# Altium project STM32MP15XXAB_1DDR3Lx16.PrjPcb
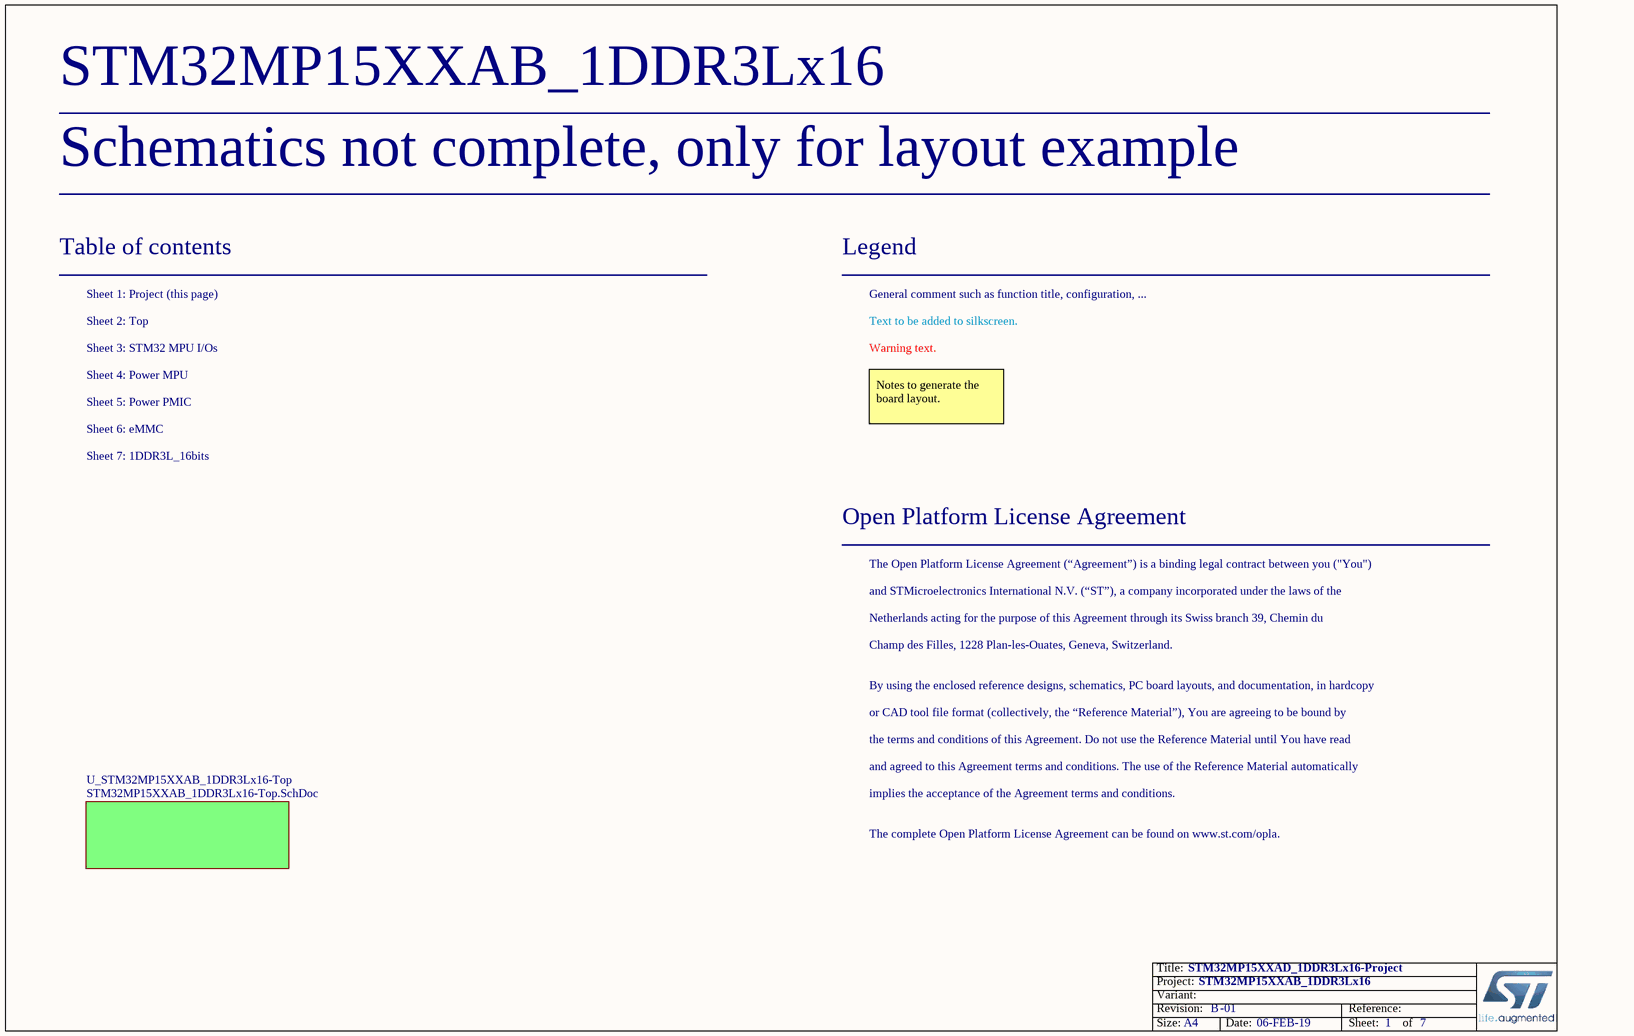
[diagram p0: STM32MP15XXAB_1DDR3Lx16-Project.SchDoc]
Board_Assembly_Revision: 01; Board_Document_Date: 06-FEB-19; Board_Name: STM32MP15XXAB_1DDR3Lx16; Board_PCB_Revision: B
7 sheets, 144 parts. Net scope: flat (ports and power ports of the same name join across sheets).
Board file: STM32MP15XXAB_1DDR3Lx16_B01.PcbDoc
Sheets:
  STM32MP15XXAB_1DDR3Lx16-Project.SchDoc
    U_STM32MP15XXAB_1DDR3Lx16-Top = STM32MP15XXAB_1DDR3Lx16-Top.SchDoc
      U_Power_PMIC = Power_PMIC.SchDoc
      U_Power_MPU = Power_MPU.SchDoc
      U_eMMC = eMMC.SchDoc
      U_STM32_MPU_IOs = STM32_MPU_IOs.SchDoc
      U_1DDR3L_16bits = 1DDR3L_16bits.SchDoc

## Sheet STM32MP15XXAB_1DDR3Lx16-Project.SchDoc: STM32MP15XXAD_1DDR3Lx16-Project
size A4; ApprovedBy: Not used; CheckedBy: Not used; Author: Not used; CompanyName: STMicroelectronics; DrawnBy: Not used; Engineer: Not used; Organization: Not used; Address1: Not used; Address2: Not used; Address3: Not used; Address4: Not used; DocumentNumber: Not used; Revision: Not used; SheetNumber: 1; SheetTotal: 7

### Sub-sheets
U_STM32MP15XXAB_1DDR3Lx16-Top = STM32MP15XXAB_1DDR3Lx16-Top.SchDoc: no entries

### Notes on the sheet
- Schematics not complete, only for layout example
- Table of contents
- Sheet 1: Project (this page)
- Legend
- General comment such as function title, configuration, ...
- Sheet 2: Top
- Sheet 3: STM32 MPU I/Os
- Sheet 4: Power MPU
- Text to be added to silkscreen.
- Warning text.
- Sheet 5: Power PMIC
- Sheet 6: eMMC
- Notes to generate the board layout.
- Sheet 7: 1DDR3L_16bits
- Open Platform License Agreement
- The Open Platform License Agreement (“Agreement”) is a binding legal contract between you ("You")
- and STMicroelectronics International N.V. (“ST”), a company incorporated under the laws of the
- Netherlands acting for the purpose of this Agreement through its Swiss branch 39, Chemin du
- Champ des Filles, 1228 Plan-les-Ouates, Geneva, Switzerland.
- By using the enclosed reference designs, schematics, PC board layouts, and documentation, in hardcopy
- or CAD tool file format (collectively, the “Reference Material”), You are agreeing to be bound by
- the terms and conditions of this Agreement. Do not use the Reference Material until You have read
- and agreed to this Agreement terms and conditions. The use of the Reference Material automatically
- implies the acceptance of the Agreement terms and conditions.
- The complete Open Platform License Agreement can be found on www.st.com/opla.

## Sheet STM32MP15XXAB_1DDR3Lx16-Top.SchDoc: STM32MP15XXAD_1DDR3Lx16-TOP
size A4; Date: Not used; ApprovedBy: Not used; CheckedBy: Not used; Author: Not used; CompanyName: STMicroelectronics; DrawnBy: Not used; Engineer: Not used; Organization: Not used; Address1: Not used; Address2: Not used; Address3: Not used; Address4: Not used; DocumentNumber: Not used; Revision: Not used; SheetNumber: 2; SheetTotal: 7
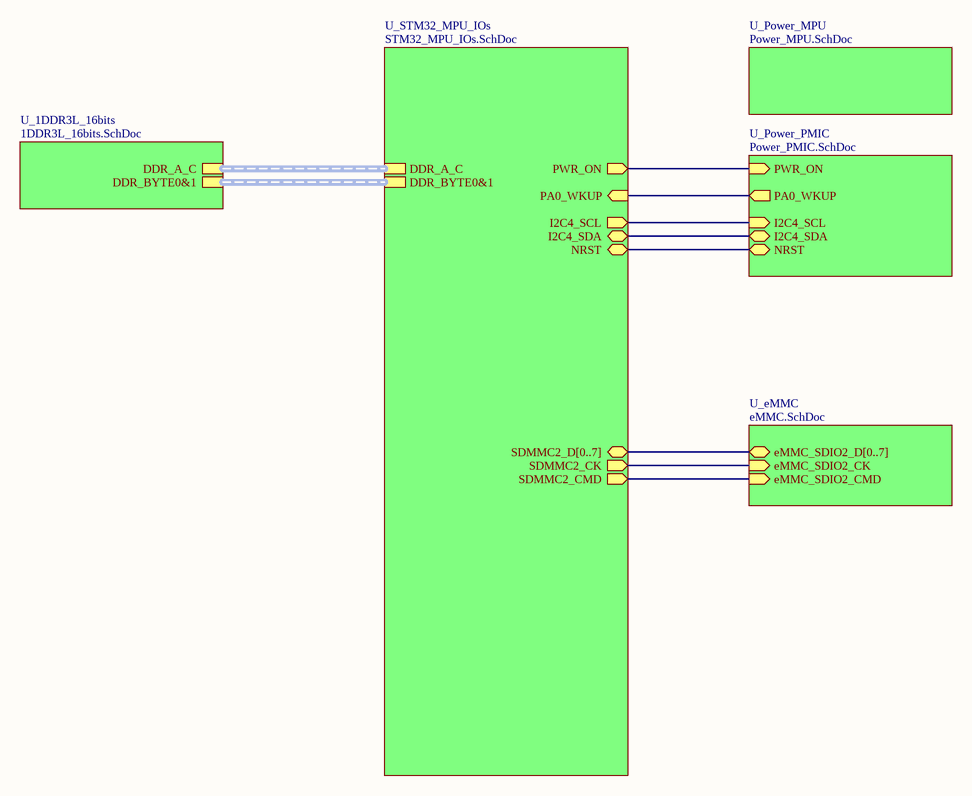
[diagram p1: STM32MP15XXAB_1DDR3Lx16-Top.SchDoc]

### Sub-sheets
U_1DDR3L_16bits = 1DDR3L_16bits.SchDoc: DDR_BYTE0&1 (harness DDR_BYTE_0&1), DDR_A_C (harness DDR_A_C)
U_eMMC = eMMC.SchDoc: eMMC_SDIO2_CK (in), eMMC_SDIO2_D[0..7] (bidir), eMMC_SDIO2_CMD (in)
U_Power_MPU = Power_MPU.SchDoc: no entries
U_Power_PMIC = Power_PMIC.SchDoc: I2C4_SDA (bidir), I2C4_SCL (in), PA0_WKUP (out), NRST (bidir), PWR_ON (in)
U_STM32_MPU_IOs = STM32_MPU_IOs.SchDoc: PA0_WKUP (in), NRST (bidir), PWR_ON (out), I2C4_SCL (out), I2C4_SDA (bidir), DDR_BYTE0&1 (harness DDR_BYTE_0&1), DDR_A_C (harness DDR_A_C), SDMMC2_D[0..7] (bidir), SDMMC2_CMD (out), SDMMC2_CK (out)

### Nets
(unnamed): sheet U_Power_PMIC/I2C4_SDA, sheet U_STM32_MPU_IOs/I2C4_SDA
(unnamed): sheet U_Power_PMIC/I2C4_SCL, sheet U_STM32_MPU_IOs/I2C4_SCL  [a separate net that carries the same name]
(unnamed): sheet U_Power_PMIC/PA0_WKUP, sheet U_STM32_MPU_IOs/PA0_WKUP  [a separate net that carries the same name]
(unnamed): sheet U_Power_PMIC/NRST, sheet U_STM32_MPU_IOs/NRST  [a separate net that carries the same name]
(unnamed): sheet U_Power_PMIC/PWR_ON, sheet U_STM32_MPU_IOs/PWR_ON  [a separate net that carries the same name]
(unnamed): sheet U_eMMC/eMMC_SDIO2_CK, sheet U_STM32_MPU_IOs/SDMMC2_CK  [a separate net that carries the same name]
(unnamed): sheet U_eMMC/eMMC_SDIO2_CMD, sheet U_STM32_MPU_IOs/SDMMC2_CMD  [a separate net that carries the same name]

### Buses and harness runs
bus sheet U_eMMC/eMMC_SDIO2_D[0..7] = sheet U_STM32_MPU_IOs/SDMMC2_D[0..7]
harness sheet U_1DDR3L_16bits/DDR_A_C = sheet U_STM32_MPU_IOs/DDR_A_C
harness sheet U_1DDR3L_16bits/DDR_BYTE0&1 = sheet U_STM32_MPU_IOs/DDR_BYTE0&1

## Sheet Power_PMIC.SchDoc: Power_PMIC
size A3; CompanyName: STMicroelectronics; Organization: Microcontrollers Division; Address1: 12, Rue Jules HOROWITZ; Address2: 38019 Grenoble; Address3: FRANCE; SheetNumber: 5; SheetTotal: 7
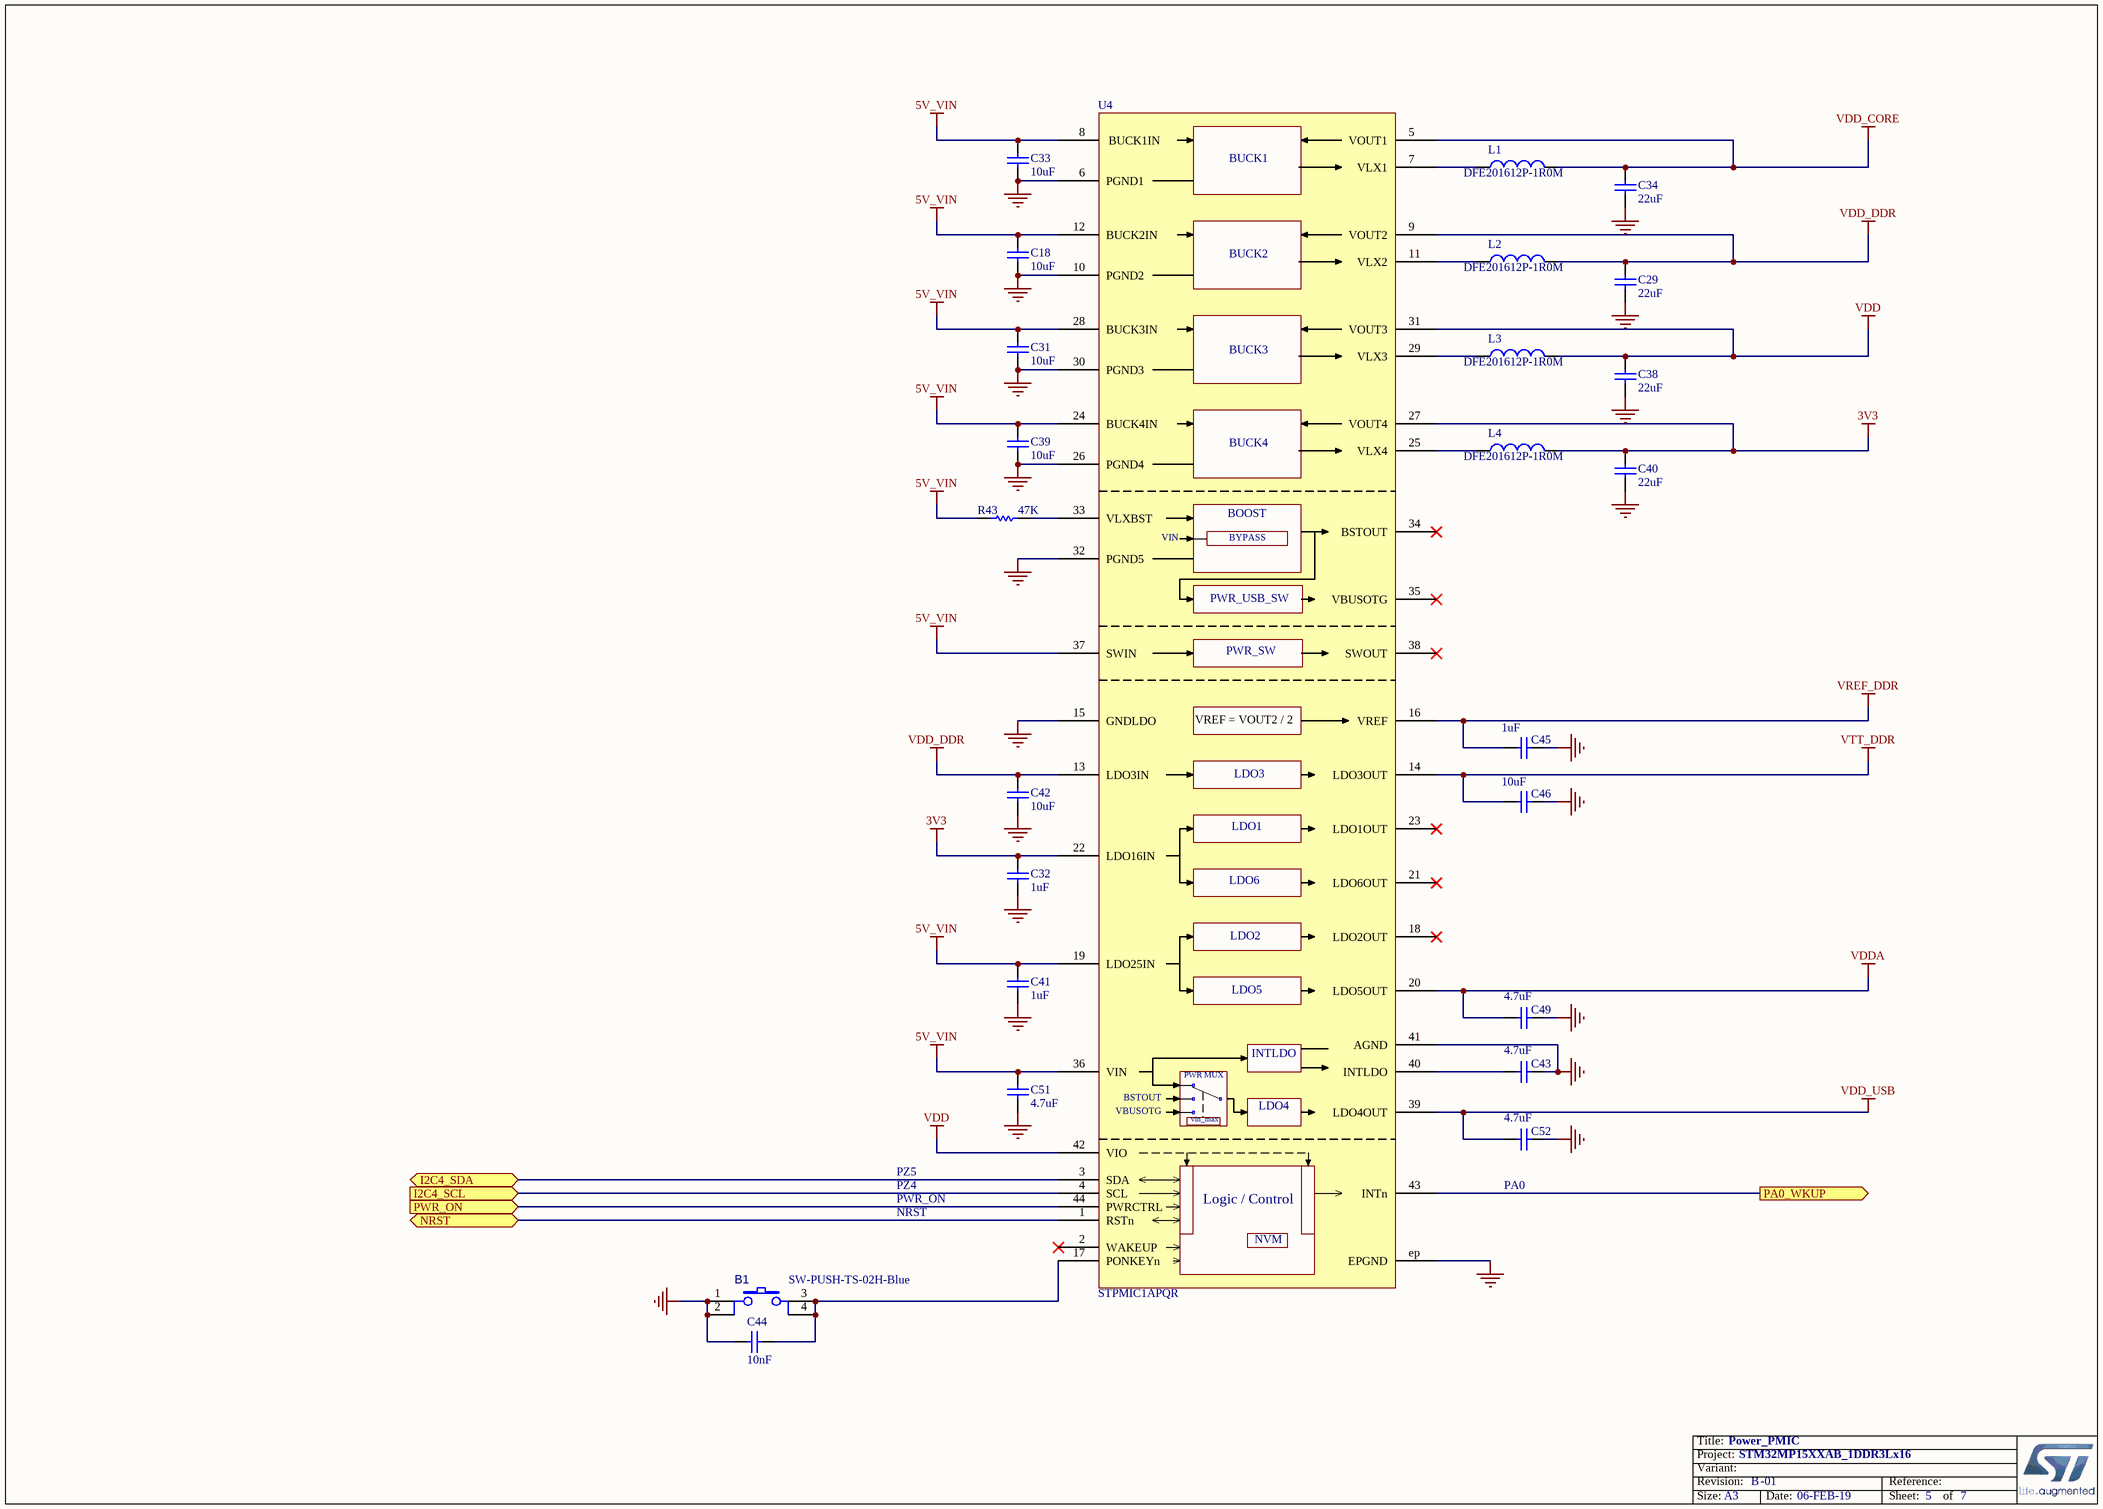
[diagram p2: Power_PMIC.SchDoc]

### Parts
B1  value SW-PUSH-TS-02H-Blue  [SWI_JIUBABA_C-TS-02H-2-5-B-V-T_R_BLUE]
C18  value 10uF  [C0603]
C29  value 22uF  [C0603]
C31  value 10uF  [C0603]
C32  value 1uF  [C0402]
C33  value 10uF  [C0603]
C34  value 22uF  [C0603]
C38  value 22uF  [C0603]
C39  value 10uF  [C0603]
C40  value 22uF  [C0603]
C41  value 1uF  [C0402]
C42  value 10uF  [C0603]
C43  value 4.7uF  [C0402]
C44  value 10nF  [C0402]
C45  value 1uF  [C0402]
C46  value 10uF  [C0603]
C49  value 4.7uF  [C0402]
C51  value 4.7uF  [C0402]
C52  value 4.7uF  [C0402]
L1  value DFE201612P-1R0M  [IND_MURATA_DFE201612P]
L2  value DFE201612P-1R0M  [IND_MURATA_DFE201612P]
L3  value DFE201612P-1R0M  [IND_MURATA_DFE201612P]
L4  value DFE201612P-1R0M  [IND_MURATA_DFE201612P]
R43  value 47K  [R0402]
U4  value STPMIC1APQR  [ICC_WFQFN44-EPAD_5X6_P040]

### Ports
I2C4_SCL (in), I2C4_SDA (bidir), NRST (bidir), PA0_WKUP (out), PWR_ON (in)

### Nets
3V3: C32.2 C40.2 L4.2 U4.22(LDO16IN) U4.27(VOUT4)
5V_VIN: C18.2 C31.2 C33.2 C39.2 C41.2 C51.1 R43.2 U4.8(BUCK1IN) U4.12(BUCK2IN) U4.19(LDO25IN) U4.24(BUCK4IN) U4.28(BUCK3IN) U4.36(VIN) U4.37(SWIN)
GND: B1.1 B1.2 C18.1 C29.1 C31.1 C32.1 C33.1 C34.1 C38.1 C39.1 C40.1 C41.1 C42.1 C43.1 C44.1 C45.1 C46.1 C49.1 C51.2 C52.1 U4.6(PGND1) U4.10(PGND2) U4.15(GNDLDO) U4.26(PGND4) U4.30(PGND3) U4.32(PGND5) U4.41(AGND) U4.ep(EPGND)
VDD: C38.2 L3.2 U4.31(VOUT3) U4.42(VIO)
VDD_CORE: C34.2 L1.2 U4.5(VOUT1)
VDD_DDR: C29.2 C42.2 L2.2 U4.9(VOUT2) U4.13(LDO3IN)
VDD_USB: C52.2 U4.39(LDO4OUT)
VDDA: C49.2 U4.20(LDO5OUT)
VREF_DDR: C45.2 U4.16(VREF)
VTT_DDR: C46.2 U4.14(LDO3OUT)
I2C4_SCL: U4.4(SCL) ; port I2C4_SCL
I2C4_SDA: U4.3(SDA) ; port I2C4_SDA
NRST: U4.1(RSTn) ; port NRST
PA0_WKUP: U4.43(INTn) ; port PA0_WKUP
PWR_ON: U4.44(PWRCTRL) ; port PWR_ON
NetB1_3: B1.3 B1.4 C44.2 U4.17(PONKEYn)
NetC43_2: C43.2 U4.40(INTLDO)
NetL1_1: L1.1 U4.7(VLX1)
NetL2_1: L2.1 U4.11(VLX2)
NetL3_1: L3.1 U4.29(VLX3)
NetL4_1: L4.1 U4.25(VLX4)
NetR43_1: R43.1 U4.33(VLXBST)

Not connected (* = marked no-connect by the designer): U4 2(WAKEUP)* 18(LDO2OUT)* 21(LDO6OUT)* 23(LDO1OUT)* 34(BSTOUT)* 35(VBUSOTG)* 38(SWOUT)*

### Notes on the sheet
- PZ5
- PZ4
- (near C52) PA0
- NRST
- PWR_ON

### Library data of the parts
B1 = MCD-00172: Switch HW SMD blue; Part_Type: Misc; Manufacturer_Part_Number: C-TS-02H-2.5-B-V-T/R BLUE; Manufacturer: JIUBABA; Provided_By: SUBCO
C18 C31 C33 C39 C42 C46 = MCD-00099: Capacitor, MLCC, 10uF, 10V, X5R, 10%, 0603, T=0,8mm; Manufacturer_Part_Number: GRM188R61A106KE69D; Manufacturer: MURATA; Provided_By: SUBCO; ECCN_US: EAR99; ECCN_EU: NEC
C29 C34 C38 C40 = MCD-00100: Capacitor, MLCC, 22uF, 6V3, X5R, 20%, 0603, T=0,8mm; Manufacturer_Part_Number: GRM188R60J226MEA0J; Manufacturer: MURATA; Provided_By: SUBCO; ECCN_US: EAR99; ECCN_EU: NEC
C32 C41 C45 = MCD-00095: Capacitor, MLCC, 1uF, 6V3, X5R, 10%, 0402, T=0,5mm; Manufacturer_Part_Number: GRM155R61E105KA12; Manufacturer: MURATA; Alternate_Manufacturer_Part_Number: GRM155R60J105KE19; Provided_By: SUBCO; ECCN_US: EAR99; ECCN_EU: NEC
C43 C49 C51 C52 = MCD-01356: Capacitor, MLCC, 4.7uF, 6V3, X5R, 20%, 0402, T=0,5mm; Manufacturer_Part_Number: GRM155R60J475ME47; Manufacturer: MURATA; Provided_By: SUBCO; ECCN_US: EAR99; ECCN_EU: NEC
C44 = MCD-00011: Capacitor, MLCC, 10nF, 16V, X7R, 10%, 0402, T=0.5mm; Manufacturer_Part_Number: CC0402KRX7R7BB103; Manufacturer: YAGEO; Provided_By: SUBCO; ECCN_US: EAR99; ECCN_EU: NEC
L1-L4 = MCD-01491: Inductors 1.0uH 54mOhms3.3A +/-20% 2016; Manufacturer: MURATA; Provided_By: SUBCO
R43 = MCD-00063: Resistor,47K,0402,1%,1/16W; Manufacturer_Part_Number: RC0402FR-0747KL; Manufacturer: YAGEO; Provided_By: SUBCO; ECCN_US: EAR99; ECCN_EU: NEC
U4 = MCD-01650: ST PMIC:  4 step-down + 1 advanced boost SMPS, 6 LDOs, 2 pwr switches, DDR Vref, NVM option 'A' for IO@3.3V; Part_Type: IC; Manufacturer: STMICROELECTRONICS; ECCN_US: EAR99; ECCN_EU: NEC; Provided_By: SUBCO with ST control

## Sheet Power_MPU.SchDoc: Power_MPU
size A3; CompanyName: STMicroelectronics; SheetNumber: 4; SheetTotal: 7
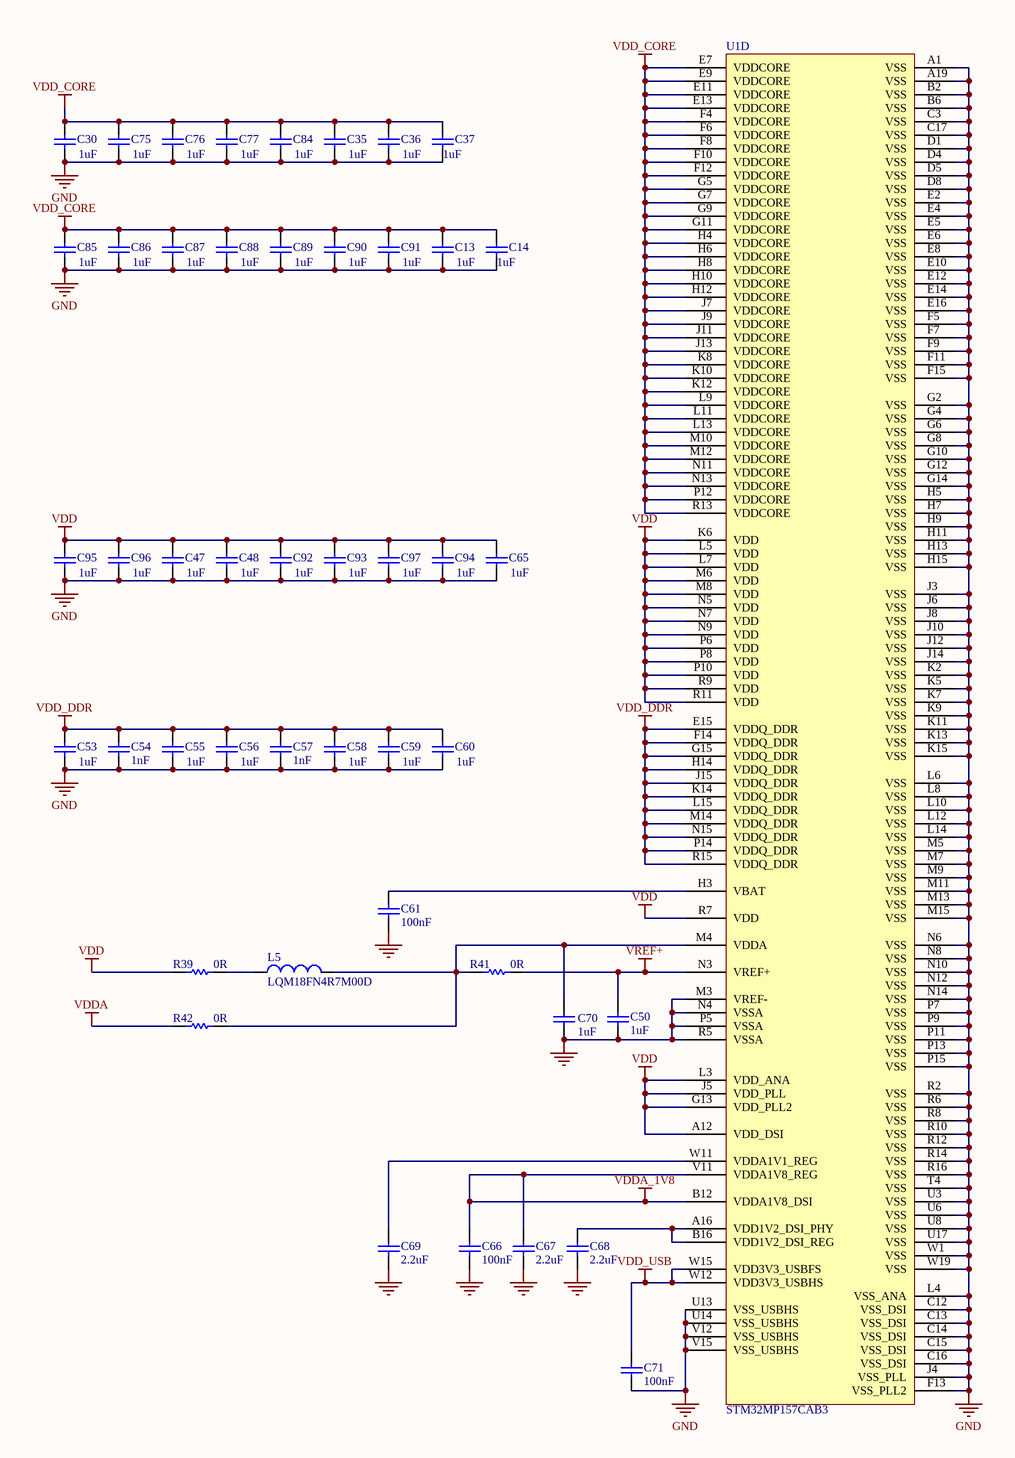
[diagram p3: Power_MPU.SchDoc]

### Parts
C13  value 1uF  [C0402]
C14  value 1uF  [C0402]
C30  value 1uF  [C0402]
C35  value 1uF  [C0402]
C36  value 1uF  [C0402]
C37  value 1uF  [C0402]
C47  value 1uF  [C0402]
C48  value 1uF  [C0402]
C50  value 1uF  [C0402]
C53  value 1uF  [C0402]
C54  value 1nF  [C0402]
C55  value 1uF  [C0402]
C56  value 1uF  [C0402]
C57  value 1nF  [C0402]
C58  value 1uF  [C0402]
C59  value 1uF  [C0402]
C60  value 1uF  [C0402]
C61  value 100nF  [C0402]
C65  value 1uF  [C0402]
C66  value 100nF  [C0402]
C67  value 2.2uF  [C0402]  (hidden comment: Capacitor)
C68  value 2.2uF  [C0402]  (hidden comment: Capacitor)
C69  value 2.2uF  [C0402]  (hidden comment: Capacitor)
C70  value 1uF  [C0402]
C71  value 100nF  [C0402]
C75  value 1uF  [C0402]
C76  value 1uF  [C0402]
C77  value 1uF  [C0402]
C84  value 1uF  [C0402]
C85  value 1uF  [C0402]
C86  value 1uF  [C0402]
C87  value 1uF  [C0402]
C88  value 1uF  [C0402]
C89  value 1uF  [C0402]
C90  value 1uF  [C0402]
C91  value 1uF  [C0402]
C92  value 1uF  [C0402]
C93  value 1uF  [C0402]
C94  value 1uF  [C0402]
C95  value 1uF  [C0402]
C96  value 1uF  [C0402]
C97  value 1uF  [C0402]
L5  value LQM18FN4R7M00D  [L0603_H0P8]
R39  value 0R  [R0402]
R41  value 0R  [R0402]
R42  value 0R  [R0402]
U1  STM32MP157CAB3  [ICC_LFBGA354_16X16_STM32MP157CAB3_P080]  (part D of 5)

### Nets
GND: C13.1 C14.1 C30.1 C35.1 C36.1 C37.1 C47.1 C48.1 C50.1 C53.1 C54.1 C55.1 C56.1 C57.1 C58.1 C59.1 C60.1 C61.1 C65.1 C66.1 C67.1 C68.1 C69.1 C70.1 C71.1 C75.1 C76.1 C77.1 C84.1 C85.1 C86.1 C87.1 C88.1 C89.1 C90.1 C91.1 C92.1 C93.1 C94.1 C95.1 C96.1 C97.1 U1.A1(VSS) U1.A19(VSS) U1.B2(VSS) U1.B6(VSS) U1.C3(VSS) U1.C12(VSS_DSI) U1.C13(VSS_DSI) U1.C14(VSS_DSI) U1.C15(VSS_DSI) U1.C16(VSS_DSI) U1.C17(VSS) U1.D1(VSS) U1.D4(VSS) U1.D5(VSS) U1.D8(VSS) U1.E2(VSS) U1.E4(VSS) U1.E5(VSS) U1.E6(VSS) U1.E8(VSS) U1.E10(VSS) U1.E12(VSS) U1.E14(VSS) U1.E16(VSS) U1.F5(VSS) U1.F7(VSS) U1.F9(VSS) U1.F11(VSS) U1.F13(VSS_PLL2) U1.F15(VSS) U1.G2(VSS) U1.G4(VSS) U1.G6(VSS) U1.G8(VSS) U1.G10(VSS) U1.G12(VSS) U1.G14(VSS) U1.H5(VSS) U1.H7(VSS) U1.H9(VSS) U1.H11(VSS) U1.H13(VSS) U1.H15(VSS) U1.J3(VSS) U1.J4(VSS_PLL) U1.J6(VSS) U1.J8(VSS) U1.J10(VSS) U1.J12(VSS) U1.J14(VSS) U1.K2(VSS) U1.K5(VSS) U1.K7(VSS) U1.K9(VSS) U1.K11(VSS) U1.K13(VSS) U1.K15(VSS) U1.L4(VSS_ANA) U1.L6(VSS) U1.L8(VSS) U1.L10(VSS) U1.L12(VSS) U1.L14(VSS) U1.M3(VREF-) U1.M5(VSS) U1.M7(VSS) U1.M9(VSS) U1.M11(VSS) U1.M13(VSS) U1.M15(VSS) U1.N4(VSSA) U1.N6(VSS) U1.N8(VSS) U1.N10(VSS) U1.N12(VSS) U1.N14(VSS) U1.P5(VSSA) U1.P7(VSS) U1.P9(VSS) U1.P11(VSS) U1.P13(VSS) U1.P15(VSS) U1.R2(VSS) U1.R5(VSSA) U1.R6(VSS) U1.R8(VSS) U1.R10(VSS) U1.R12(VSS) U1.R14(VSS) U1.R16(VSS) U1.T4(VSS) U1.U3(VSS) U1.U6(VSS) U1.U8(VSS) U1.U13(VSS_USBHS) U1.U14(VSS_USBHS) U1.U17(VSS) U1.V12(VSS_USBHS) U1.V15(VSS_USBHS) U1.W1(VSS) U1.W19(VSS)
VDD: C47.2 C48.2 C65.2 C92.2 C93.2 C94.2 C95.2 C96.2 C97.2 R39.1 U1.A12(VDD_DSI) U1.G13(VDD_PLL2) U1.J5(VDD_PLL) U1.K6(VDD) U1.L3(VDD_ANA) U1.L5(VDD) U1.L7(VDD) U1.M6(VDD) U1.M8(VDD) U1.N5(VDD) U1.N7(VDD) U1.N9(VDD) U1.P6(VDD) U1.P8(VDD) U1.P10(VDD) U1.R7(VDD) U1.R9(VDD) U1.R11(VDD)
VDD_CORE: C13.2 C14.2 C30.2 C35.2 C36.2 C37.2 C75.2 C76.2 C77.2 C84.2 C85.2 C86.2 C87.2 C88.2 C89.2 C90.2 C91.2 U1.E7(VDDCORE) U1.E9(VDDCORE) U1.E11(VDDCORE) U1.E13(VDDCORE) U1.F4(VDDCORE) U1.F6(VDDCORE) U1.F8(VDDCORE) U1.F10(VDDCORE) U1.F12(VDDCORE) U1.G5(VDDCORE) U1.G7(VDDCORE) U1.G9(VDDCORE) U1.G11(VDDCORE) U1.H4(VDDCORE) U1.H6(VDDCORE) U1.H8(VDDCORE) U1.H10(VDDCORE) U1.H12(VDDCORE) U1.J7(VDDCORE) U1.J9(VDDCORE) U1.J11(VDDCORE) U1.J13(VDDCORE) U1.K8(VDDCORE) U1.K10(VDDCORE) U1.K12(VDDCORE) U1.L9(VDDCORE) U1.L11(VDDCORE) U1.L13(VDDCORE) U1.M10(VDDCORE) U1.M12(VDDCORE) U1.N11(VDDCORE) U1.N13(VDDCORE) U1.P12(VDDCORE) U1.R13(VDDCORE)
VDD_DDR: C53.2 C54.2 C55.2 C56.2 C57.2 C58.2 C59.2 C60.2 U1.E15(VDDQ_DDR) U1.F14(VDDQ_DDR) U1.G15(VDDQ_DDR) U1.H14(VDDQ_DDR) U1.J15(VDDQ_DDR) U1.K14(VDDQ_DDR) U1.L15(VDDQ_DDR) U1.M14(VDDQ_DDR) U1.N15(VDDQ_DDR) U1.P14(VDDQ_DDR) U1.R15(VDDQ_DDR)
VDD_USB: C71.2 U1.W12(VDD3V3_USBHS) U1.W15(VDD3V3_USBFS)
VDDA: R42.1
VDDA_1V8: C66.2 C67.2 U1.B12(VDDA1V8_DSI) U1.V11(VDDA1V8_REG)
VREF+: C50.2 R41.2 U1.N3(VREF+)
NetC61_2: C61.2 U1.H3(VBAT)
NetC68_2: C68.2 U1.A16(VDD1V2_DSI_PHY) U1.B16(VDD1V2_DSI_REG)
NetC69_2: C69.2 U1.W11(VDDA1V1_REG)
NetC70_2: C70.2 L5.2 R41.1 R42.2 U1.M4(VDDA)
NetL5_1: L5.1 R39.2

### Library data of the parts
C13 C14 C30 C35-C37 C47 C48 C50 C53 C55 C56 C58-C60 C65 C70 C75-C77 C84-C97 = MCD-00095: as C32 on sheet Power_PMIC
C54 C57 = MCD-00198: Capacitor, MLCC, 1nF, 16V, X7R, 10%, 0402, T=0.5mm; Manufacturer_Part_Number: CC0402KRX7R7BB102; Manufacturer: YAGEO; Provided_By: SUBCO; ECCN_US: EAR99; ECCN_EU: NEC
C61 C66 C71 = MCD-00006: Capacitor, MLCC, 100nF, 16V, X7R, 10%, 0402, T=0.5mm; Manufacturer_Part_Number: CC0402KRX7R7BB104; Manufacturer: YAGEO; Alternate_Manufacturer_Part_Number: GCM155R71C104KA55D; Alternate_Manufacturer: MURATA; Provided_By: SUBCO; ECCN_US: EAR99; ECCN_EU: NEC
C67-C69 = MCD-01823: Capacitor,MLCC,2.2uF,6V3,X5R,10%,0402,T=0.5; Manufacturer_Part_Number: GRM155R60J225KE95D; Manufacturer: MURATA; ECCN_US: EAR99; ECCN_EU: NEC; Provided_By: SUBCO
L5 = MCD-01134: IND 4.7uH 20% 80mA 600mhom 0603; Part_Type: Inductor; Manufacturer: MURATA; Provided_By: SUBCO
R39 R41 R42 = MCD-00052: Resistor,0R,0402,5%,1/16W; Manufacturer_Part_Number: RC0402JR-070RL; Manufacturer: YAGEO; Provided_By: SUBCO; ECCN_US: EAR99; ECCN_EU: NEC
U1 = MCD-01805: MPU LFBGA 16x16x1.271 PITCH 0.8 mm secure boot + crypto; Part_Type: IC; Manufacturer: STMICROELECTRONICS; ECCN_US: 5A992C; ECCN_EU: 5A002A4; Provided_By: SUBCO with ST control; Company_Nationality: Netherlands; CCATS: G179243   5A992C 740.17(B)(3) 25-Mar-2019; Component_Country_Of_Origin: Korea (South)

## Sheet eMMC.SchDoc: eMMC
size A3; CompanyName: STMicroelectronics; Address1: 12, Rue Jules HOROWITZ; Address2: 38019 Grenoble; Address3: FRANCE; SheetNumber: 6; SheetTotal: 7
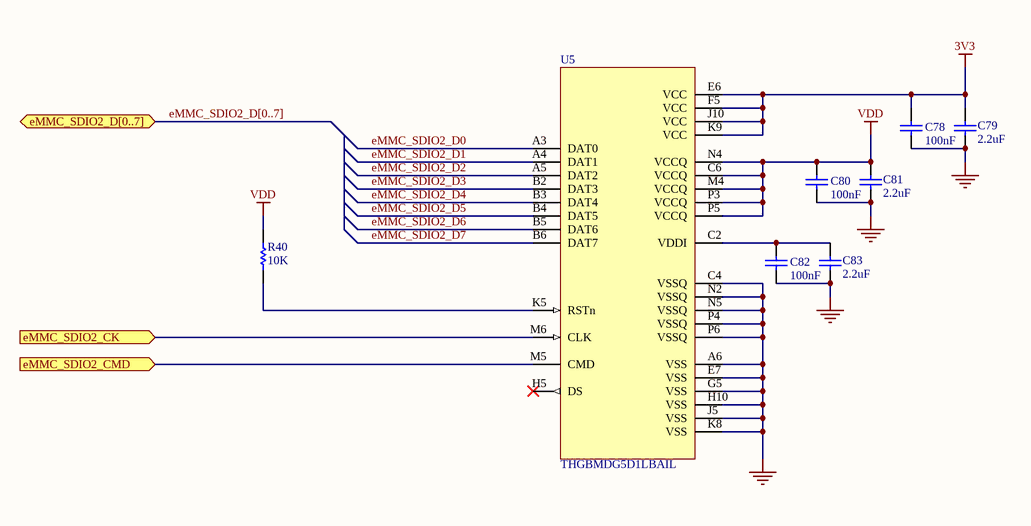
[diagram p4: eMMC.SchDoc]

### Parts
C78  value 100nF  [C0402]
C79  value 2.2uF  [C0603]
C80  value 100nF  [C0402]
C81  value 2.2uF  [C0603]
C82  value 100nF  [C0402]
C83  value 2.2uF  [C0603]
R40  value 10K  [R0402]
U5  value THGBMDG5D1LBAIL  [ICC_P-WFBGA153_13X11P5_P050]

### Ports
eMMC_SDIO2_CK (in), eMMC_SDIO2_CMD (in), eMMC_SDIO2_D[0..7] (bidir)

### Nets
3V3: C78.2 C79.2 U5.E6(VCC) U5.F5(VCC) U5.J10(VCC) U5.K9(VCC)
GND: C78.1 C79.1 C80.1 C81.1 C82.1 C83.1 U5.A6(VSS) U5.C4(VSSQ) U5.E7(VSS) U5.G5(VSS) U5.H10(VSS) U5.J5(VSS) U5.K8(VSS) U5.N2(VSSQ) U5.N5(VSSQ) U5.P4(VSSQ) U5.P6(VSSQ)
VDD: C80.2 C81.2 R40.2 U5.C6(VCCQ) U5.M4(VCCQ) U5.N4(VCCQ) U5.P3(VCCQ) U5.P5(VCCQ)
eMMC_SDIO2_CK: U5.M6(CLK) ; port eMMC_SDIO2_CK
eMMC_SDIO2_CMD: U5.M5(CMD) ; port eMMC_SDIO2_CMD
eMMC_SDIO2_D0: U5.A3(DAT0)
eMMC_SDIO2_D1: U5.A4(DAT1)
eMMC_SDIO2_D2: U5.A5(DAT2)
eMMC_SDIO2_D3: U5.B2(DAT3)
eMMC_SDIO2_D4: U5.B3(DAT4)
eMMC_SDIO2_D5: U5.B4(DAT5)
eMMC_SDIO2_D6: U5.B5(DAT6)
eMMC_SDIO2_D7: U5.B6(DAT7)
NetC82_2: C82.2 C83.2 U5.C2(VDDI)
NetR40_1: R40.1 U5.K5(RSTn)

Not connected (* = marked no-connect by the designer): U5 H5(DS)*

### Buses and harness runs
bus eMMC_SDIO2_D[0..7] = port eMMC_SDIO2_D[0..7]

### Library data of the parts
C78 C80 C82 = MCD-00006: as C61 on sheet Power_MPU
C79 C81 C83 = MCD-00012: Capacitor, MLCC, 2.2uF, 10V, X5R, 10%, 0603, T=0,8mm; Manufacturer_Part_Number: CC0603KRX5R6BB225; Manufacturer: YAGEO; Alternate_Manufacturer_Part_Number: C0603C225K8PACTU; Alternate_Manufacturer: KEMET; Provided_By: SUBCO; ECCN_US: EAR99; ECCN_EU: NEC
R40 = MCD-00053: Resistor,10K,0402,1%,1/16W; Manufacturer_Part_Number: RC0402FR-0710KL; Manufacturer: YAGEO; Provided_By: SUBCO; ECCN_US: EAR99; ECCN_EU: NEC
U5 = MCD-00110: Memory,e-MMC,4GB,3V3,WFBGA,153pins; Part_Type: IC; Manufacturer: TOSHIBA; Provided_By: SUBCO; ECCN_US: 3A991; ECCN_EU: NEC

## Sheet STM32_MPU_IOs.SchDoc: MPU
size A3; SheetNumber: 3; SheetTotal: 7
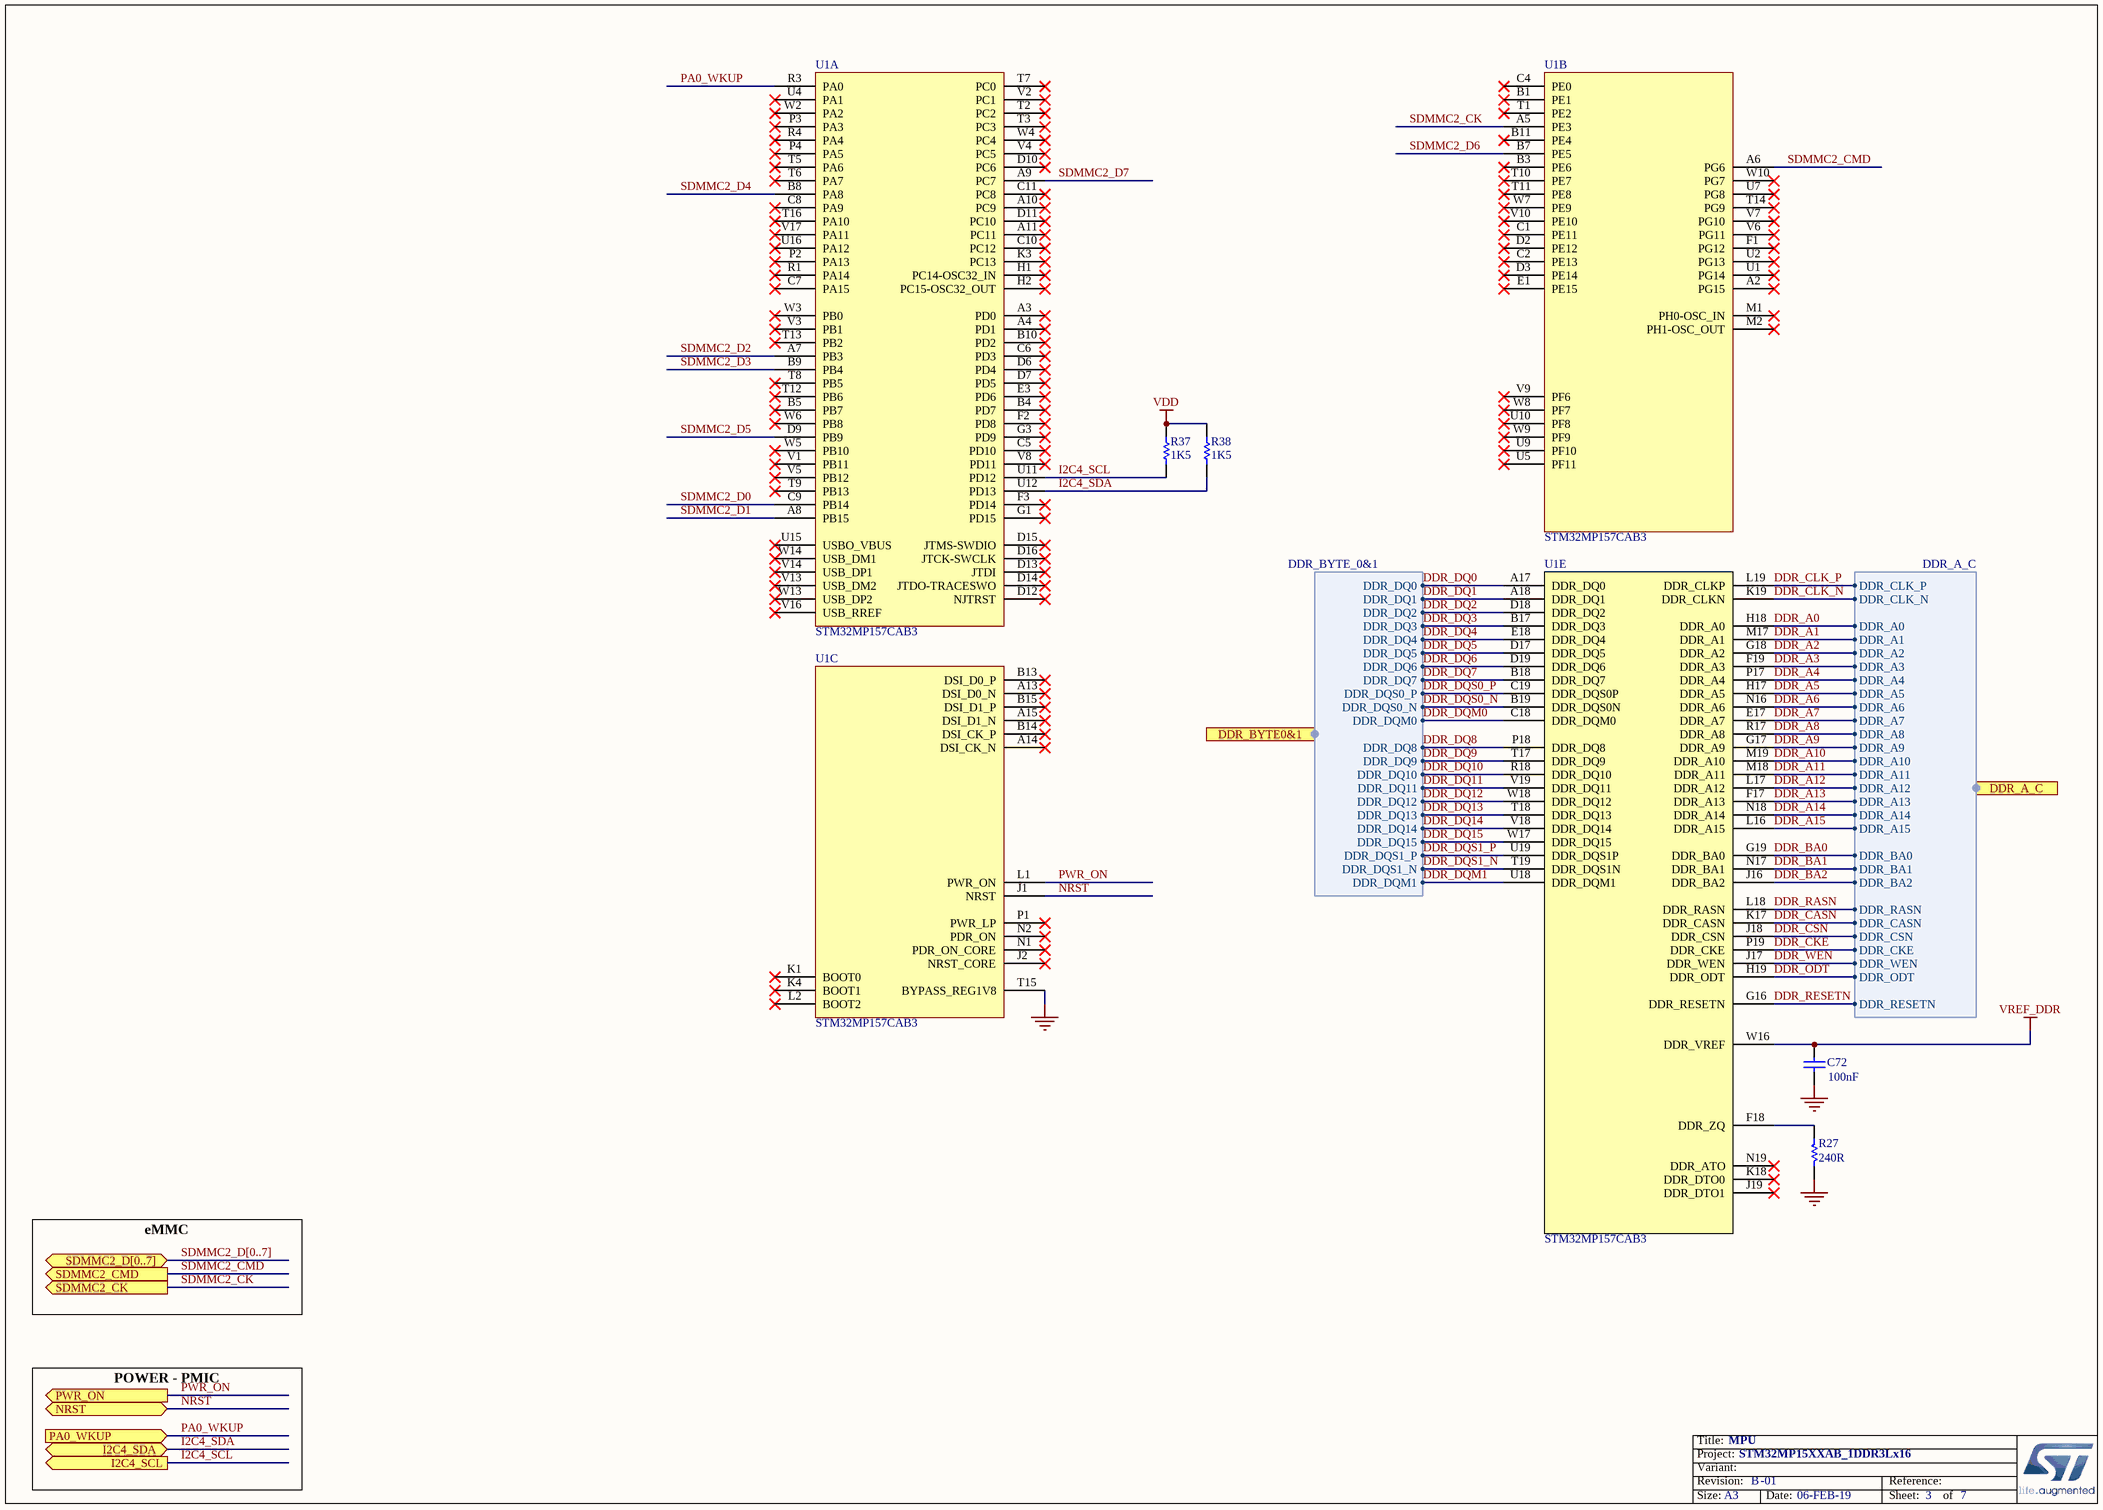
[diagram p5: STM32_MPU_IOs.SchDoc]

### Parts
C72  value 100nF  [C0402]
R27  value 240R  [R0402]
R37  value 1K5  [R0402]
R38  value 1K5  [R0402]
U1  STM32MP157CAB3  [ICC_LFBGA354_16X16_STM32MP157CAB3_P080]  (parts A,B,C,E of 5)

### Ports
DDR_A_C (harness DDR_A_C), DDR_BYTE0&1 (harness DDR_BYTE_0&1), I2C4_SCL (out), I2C4_SDA (bidir), NRST (bidir), PA0_WKUP (in), PWR_ON (out), SDMMC2_CK (out), SDMMC2_CMD (out), SDMMC2_D[0..7] (bidir)

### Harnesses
DDR_BYTE_0&1: DDR_DQ0, DDR_DQ1, DDR_DQ2, DDR_DQ3, DDR_DQ4, DDR_DQ5, DDR_DQ6, DDR_DQ7, DDR_DQS0_P, DDR_DQS0_N, DDR_DQM0, DDR_DQ8, DDR_DQ9, DDR_DQ10, DDR_DQ11, DDR_DQ12, DDR_DQ13, DDR_DQ14, DDR_DQ15, DDR_DQS1_P, DDR_DQS1_N, DDR_DQM1
DDR_A_C: DDR_CLK_P, DDR_CLK_N, DDR_A0, DDR_A1, DDR_A2, DDR_A3, DDR_A4, DDR_A5, DDR_A6, DDR_A7, DDR_A8, DDR_A9, DDR_A10, DDR_A11, DDR_A12, DDR_A13, DDR_A14, DDR_BA0, DDR_BA1, DDR_BA2, DDR_RASN, DDR_CASN, DDR_CSN, DDR_CKE, DDR_WEN, DDR_ODT, DDR_RESETN, DDR_A15

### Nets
GND: C72.1 R27.2 U1.T15(BYPASS_REG1V8)
VDD: R37.1 R38.1
VREF_DDR: C72.2 U1.W16(DDR_VREF)
DDR_A0: U1.H18(DDR_A0) ; port DDR_A_C.DDR_A0
DDR_A1: U1.M17(DDR_A1) ; port DDR_A_C.DDR_A1
DDR_A2: U1.G18(DDR_A2) ; port DDR_A_C.DDR_A2
DDR_A3: U1.F19(DDR_A3) ; port DDR_A_C.DDR_A3
DDR_A4: U1.P17(DDR_A4) ; port DDR_A_C.DDR_A4
DDR_A5: U1.H17(DDR_A5) ; port DDR_A_C.DDR_A5
DDR_A6: U1.N16(DDR_A6) ; port DDR_A_C.DDR_A6
DDR_A7: U1.E17(DDR_A7) ; port DDR_A_C.DDR_A7
DDR_A8: U1.R17(DDR_A8) ; port DDR_A_C.DDR_A8
DDR_A9: U1.G17(DDR_A9) ; port DDR_A_C.DDR_A9
DDR_A10: U1.M19(DDR_A10) ; port DDR_A_C.DDR_A10
DDR_A11: U1.M18(DDR_A11) ; port DDR_A_C.DDR_A11
DDR_A12: U1.L17(DDR_A12) ; port DDR_A_C.DDR_A12
DDR_A13: U1.F17(DDR_A13) ; port DDR_A_C.DDR_A13
DDR_A14: U1.N18(DDR_A14) ; port DDR_A_C.DDR_A14
DDR_A15: U1.L16(DDR_A15) ; port DDR_A_C.DDR_A15
DDR_BA0: U1.G19(DDR_BA0) ; port DDR_A_C.DDR_BA0
DDR_BA1: U1.N17(DDR_BA1) ; port DDR_A_C.DDR_BA1
DDR_BA2: U1.J16(DDR_BA2) ; port DDR_A_C.DDR_BA2
DDR_CASN: U1.K17(DDR_CASN) ; port DDR_A_C.DDR_CASN
DDR_CKE: U1.P19(DDR_CKE) ; port DDR_A_C.DDR_CKE
DDR_CLK_N: U1.K19(DDR_CLKN) ; port DDR_A_C.DDR_CLK_N
DDR_CLK_P: U1.L19(DDR_CLKP) ; port DDR_A_C.DDR_CLK_P
DDR_CSN: U1.J18(DDR_CSN) ; port DDR_A_C.DDR_CSN
DDR_DQ0: U1.A17(DDR_DQ0) ; port DDR_BYTE0&1.DDR_DQ0
DDR_DQ1: U1.A18(DDR_DQ1) ; port DDR_BYTE0&1.DDR_DQ1
DDR_DQ2: U1.D18(DDR_DQ2) ; port DDR_BYTE0&1.DDR_DQ2
DDR_DQ3: U1.B17(DDR_DQ3) ; port DDR_BYTE0&1.DDR_DQ3
DDR_DQ4: U1.E18(DDR_DQ4) ; port DDR_BYTE0&1.DDR_DQ4
DDR_DQ5: U1.D17(DDR_DQ5) ; port DDR_BYTE0&1.DDR_DQ5
DDR_DQ6: U1.D19(DDR_DQ6) ; port DDR_BYTE0&1.DDR_DQ6
DDR_DQ7: U1.B18(DDR_DQ7) ; port DDR_BYTE0&1.DDR_DQ7
DDR_DQ8: U1.P18(DDR_DQ8) ; port DDR_BYTE0&1.DDR_DQ8
DDR_DQ9: U1.T17(DDR_DQ9) ; port DDR_BYTE0&1.DDR_DQ9
DDR_DQ10: U1.R18(DDR_DQ10) ; port DDR_BYTE0&1.DDR_DQ10
DDR_DQ11: U1.V19(DDR_DQ11) ; port DDR_BYTE0&1.DDR_DQ11
DDR_DQ12: U1.W18(DDR_DQ12) ; port DDR_BYTE0&1.DDR_DQ12
DDR_DQ13: U1.T18(DDR_DQ13) ; port DDR_BYTE0&1.DDR_DQ13
DDR_DQ14: U1.V18(DDR_DQ14) ; port DDR_BYTE0&1.DDR_DQ14
DDR_DQ15: U1.W17(DDR_DQ15) ; port DDR_BYTE0&1.DDR_DQ15
DDR_DQM0: U1.C18(DDR_DQM0) ; port DDR_BYTE0&1.DDR_DQM0
DDR_DQM1: U1.U18(DDR_DQM1) ; port DDR_BYTE0&1.DDR_DQM1
DDR_DQS0_N: U1.B19(DDR_DQS0N) ; port DDR_BYTE0&1.DDR_DQS0_N
DDR_DQS0_P: U1.C19(DDR_DQS0P) ; port DDR_BYTE0&1.DDR_DQS0_P
DDR_DQS1_N: U1.T19(DDR_DQS1N) ; port DDR_BYTE0&1.DDR_DQS1_N
DDR_DQS1_P: U1.U19(DDR_DQS1P) ; port DDR_BYTE0&1.DDR_DQS1_P
DDR_ODT: U1.H19(DDR_ODT) ; port DDR_A_C.DDR_ODT
DDR_RASN: U1.L18(DDR_RASN) ; port DDR_A_C.DDR_RASN
DDR_RESETN: U1.G16(DDR_RESETN) ; port DDR_A_C.DDR_RESETN
DDR_WEN: U1.J17(DDR_WEN) ; port DDR_A_C.DDR_WEN
I2C4_SCL: R37.2 U1.U11(PD12) ; port I2C4_SCL
I2C4_SDA: R38.2 U1.U12(PD13) ; port I2C4_SDA
NRST: U1.J1(NRST) ; port NRST
PA0_WKUP: U1.R3(PA0) ; port PA0_WKUP
PWR_ON: U1.L1(PWR_ON) ; port PWR_ON
SDMMC2_CK: U1.A5(PE3) ; port SDMMC2_CK
SDMMC2_CMD: U1.A6(PG6) ; port SDMMC2_CMD
SDMMC2_D0: U1.C9(PB14)
SDMMC2_D1: U1.A8(PB15)
SDMMC2_D2: U1.A7(PB3)
SDMMC2_D3: U1.B9(PB4)
SDMMC2_D4: U1.B8(PA8)
SDMMC2_D5: U1.D9(PB9)
SDMMC2_D6: U1.B7(PE5)
SDMMC2_D7: U1.A9(PC7)
NetR27_1: R27.1 U1.F18(DDR_ZQ)

Not connected (* = marked no-connect by the designer): U1 A2(PG15)* A3(PD0)* A4(PD1)* A10(PC9)* A11(PC11)* A13(DSI_D0_N)* A14(DSI_CK_N)* A15(DSI_D1_N)* B1(PE1)* B3(PE6)* B4(PD7)* B5(PB7)* B10(PD2)* B11(PE4)* B13(DSI_D0_P)* B14(DSI_CK_P)* B15(DSI_D1_P)* C1(PE11)* C2(PE13)* C4(PE0)* C5(PD10)* C6(PD3)* C7(PA15)* C8(PA9)* C10(PC12)* C11(PC8)* D2(PE12)* D3(PE14)* D6(PD4)* D7(PD5)* D10(PC6)* D11(PC10)* D12(NJTRST)* D13(JTDI)* D14(JTDO-TRACESWO)* D15(JTMS-SWDIO)* D16(JTCK-SWCLK)* E1(PE15)* E3(PD6)* F1(PG12)* F2(PD8)* F3(PD14)* G1(PD15)* G3(PD9)* H1(PC14-OSC32_IN)* H2(PC15-OSC32_OUT)* J2(NRST_CORE)* J19(DDR_DTO1)* K1(BOOT0)* K3(PC13)* K4(BOOT1)* K18(DDR_DTO0)* L2(BOOT2)* M1(PH0-OSC_IN)* M2(PH1-OSC_OUT)* N1(PDR_ON_CORE)* N2(PDR_ON)* N19(DDR_ATO)* P1(PWR_LP)* P2(PA13)* P3(PA3)* P4(PA5)* R1(PA14)* R4(PA4)* T1(PE2)* T2(PC2)* T3(PC3)* T5(PA6)* T6(PA7)* T7(PC0)* T8(PB5)* T9(PB13)* T10(PE7)* T11(PE8)* T12(PB6)* T13(PB2)* T14(PG9)* T16(PA10)* U1(PG14)* U2(PG13)* U4(PA1)* U5(PF11)* U7(PG8)* U9(PF10)* U10(PF8)* U15(USBO_VBUS)* U16(PA12)* V1(PB11)* V2(PC1)* V3(PB1)* V4(PC5)* V5(PB12)* V6(PG11)* V7(PG10)* V8(PD11)* V9(PF6)* V10(PE10)* V13(USB_DM2)* V14(USB_DP1)* V16(USB_RREF)* V17(PA11)* W2(PA2)* W3(PB0)* W4(PC4)* W5(PB10)* W6(PB8)* W7(PE9)* W8(PF7)* W9(PF9)* W10(PG7)* W13(USB_DP2)* W14(USB_DM1)*

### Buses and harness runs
bus SDMMC2_D[0..7] = port SDMMC2_D[0..7]

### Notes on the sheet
- eMMC
- POWER - PMIC

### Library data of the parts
C72 = MCD-00006: as C61 on sheet Power_MPU
R27 = MCD-00120: Resistor,240R,0402,1%,1/16W; Manufacturer_Part_Number: RC0402FR-07240RL; Manufacturer: YAGEO; Provided_By: SUBCO; ECCN_US: EAR99; ECCN_EU: NEC
R37 R38 = MCD-00068: Resistor,1K5,0402,1%,1/16W; Manufacturer_Part_Number: RC0402FR-071K5L; Manufacturer: YAGEO; Provided_By: SUBCO; ECCN_US: EAR99; ECCN_EU: NEC
U1 = MCD-01805: as U1 on sheet Power_MPU

## Sheet 1DDR3L_16bits.SchDoc: 1DDR3L_16bits
size A3; Date: Not used; ApprovedBy: Not used; CheckedBy: Not used; Author: Not used; CompanyName: STMicroelectronics; DrawnBy: Not used; Engineer: Not used; Organization: Not used; Address1: Not used; Address2: Not used; Address3: Not used; Address4: Not used; DocumentNumber: Not used; Revision: Not used; SheetNumber: 7; SheetTotal: 7
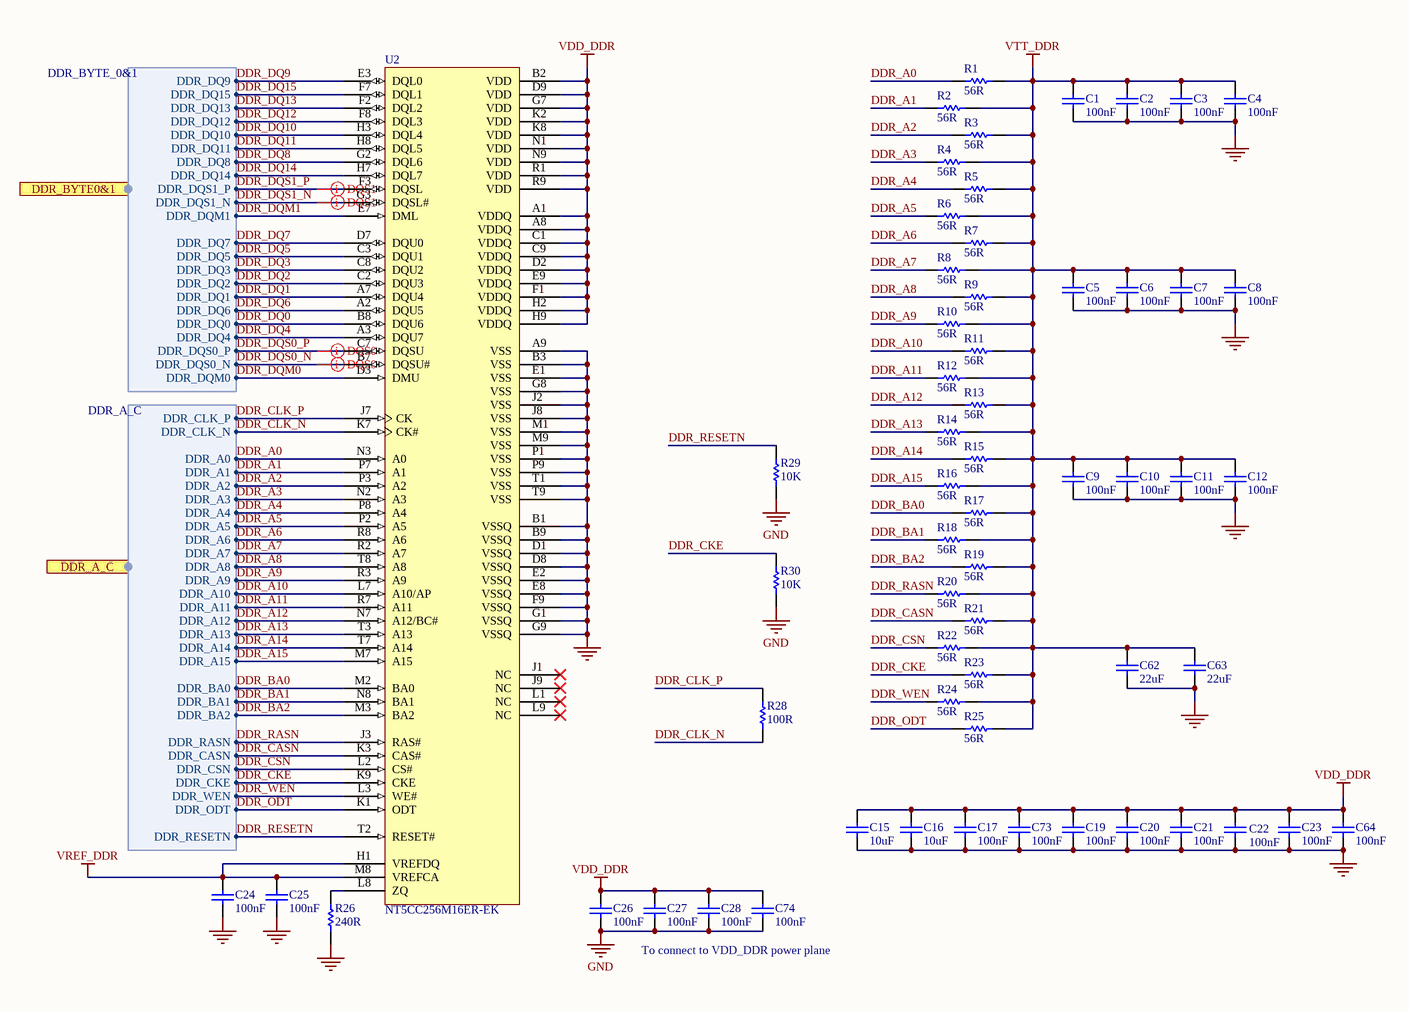
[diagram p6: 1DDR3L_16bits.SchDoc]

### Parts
C1  value 100nF  [C0402]
C2  value 100nF  [C0402]
C3  value 100nF  [C0402]
C4  value 100nF  [C0402]
C5  value 100nF  [C0402]
C6  value 100nF  [C0402]
C7  value 100nF  [C0402]
C8  value 100nF  [C0402]
C9  value 100nF  [C0402]
C10  value 100nF  [C0402]
C11  value 100nF  [C0402]
C12  value 100nF  [C0402]
C15  value 10uF  [C0603]
C16  value 10uF  [C0603]
C17  value 100nF  [C0402]
C19  value 100nF  [C0402]
C20  value 100nF  [C0402]
C21  value 100nF  [C0402]
C22  value 100nF  [C0402]
C23  value 100nF  [C0402]
C24  value 100nF  [C0402]
C25  value 100nF  [C0402]
C26  value 100nF  [C0402]
C27  value 100nF  [C0402]
C28  value 100nF  [C0402]
C62  value 22uF  [C0603]
C63  value 22uF  [C0603]
C64  value 100nF  [C0402]
C73  value 100nF  [C0402]
C74  value 100nF  [C0402]
R1  value 56R  [R0402]
R2  value 56R  [R0402]
R3  value 56R  [R0402]
R4  value 56R  [R0402]
R5  value 56R  [R0402]
R6  value 56R  [R0402]
R7  value 56R  [R0402]
R8  value 56R  [R0402]
R9  value 56R  [R0402]
R10  value 56R  [R0402]
R11  value 56R  [R0402]
R12  value 56R  [R0402]
R13  value 56R  [R0402]
R14  value 56R  [R0402]
R15  value 56R  [R0402]
R16  value 56R  [R0402]
R17  value 56R  [R0402]
R18  value 56R  [R0402]
R19  value 56R  [R0402]
R20  value 56R  [R0402]
R21  value 56R  [R0402]
R22  value 56R  [R0402]
R23  value 56R  [R0402]
R24  value 56R  [R0402]
R25  value 56R  [R0402]
R26  value 240R  [R0402]
R28  value 100R  [R0402]
R29  value 10K  [R0402]
R30  value 10K  [R0402]
U2  value NT5CC256M16ER-EK  [ICC_VFBGA96_9x13_P080]

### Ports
DDR_A_C (harness DDR_A_C), DDR_BYTE0&1 (harness DDR_BYTE_0&1)

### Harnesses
DDR_BYTE_0&1: DDR_DQ10, DDR_DQ9, DDR_DQ13, DDR_DQ15, DDR_DQ8, DDR_DQ12, DDR_DQ11, DDR_DQ14, DDR_DQS1_P, DDR_DQS1_N, DDR_DQ3, DDR_DQM1, DDR_DQ7, DDR_DQ1, DDR_DQ5, DDR_DQ2, DDR_DQ6, DDR_DQ0, DDR_DQ4, DDR_DQS0_P, DDR_DQS0_N, DDR_DQM0
DDR_A_C: DDR_A4, DDR_A0, DDR_A2, DDR_A1, DDR_A6, DDR_A3, DDR_A5, DDR_A7, DDR_A8, DDR_A9, DDR_A14, DDR_A10, DDR_A12, DDR_A11, DDR_BA0, DDR_A13, DDR_A15, DDR_BA1, DDR_BA2, DDR_RASN, DDR_CASN, DDR_CSN, DDR_CKE, DDR_WEN, DDR_ODT, DDR_CLK_P, DDR_CLK_N, DDR_RESETN

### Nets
GND: C1.1 C2.1 C3.1 C4.1 C5.1 C6.1 C7.1 C8.1 C9.1 C10.1 C11.1 C12.1 C15.1 C16.1 C17.1 C19.1 C20.1 C21.1 C22.2 C23.1 C24.1 C25.1 C26.1 C27.1 C28.1 C62.1 C63.1 C64.1 C73.1 C74.1 R26.1 R29.1 R30.1 U2.A9(VSS) U2.B1(VSSQ) U2.B3(VSS) U2.B9(VSSQ) U2.D1(VSSQ) U2.D8(VSSQ) U2.E1(VSS) U2.E2(VSSQ) U2.E8(VSSQ) U2.F9(VSSQ) U2.G1(VSSQ) U2.G8(VSS) U2.G9(VSSQ) U2.J2(VSS) U2.J8(VSS) U2.M1(VSS) U2.M9(VSS) U2.P1(VSS) U2.P9(VSS) U2.T1(VSS) U2.T9(VSS)
VDD_DDR: C15.2 C16.2 C17.2 C19.2 C20.2 C21.2 C22.1 C23.2 C26.2 C27.2 C28.2 C64.2 C73.2 C74.2 U2.A1(VDDQ) U2.A8(VDDQ) U2.B2(VDD) U2.C1(VDDQ) U2.C9(VDDQ) U2.D2(VDDQ) U2.D9(VDD) U2.E9(VDDQ) U2.F1(VDDQ) U2.G7(VDD) U2.H2(VDDQ) U2.H9(VDDQ) U2.K2(VDD) U2.K8(VDD) U2.N1(VDD) U2.N9(VDD) U2.R1(VDD) U2.R9(VDD)
VREF_DDR: C24.2 C25.2 U2.H1(VREFDQ) U2.M8(VREFCA)
VTT_DDR: C1.2 C2.2 C3.2 C4.2 C5.2 C6.2 C7.2 C8.2 C9.2 C10.2 C11.2 C12.2 C62.2 C63.2 R1.2 R2.2 R3.2 R4.2 R5.2 R6.2 R7.2 R8.2 R9.2 R10.2 R11.2 R12.2 R13.2 R14.2 R15.2 R16.2 R17.2 R18.2 R19.2 R20.2 R21.2 R22.2 R23.2 R24.2 R25.2
DDR_A0: R1.1 U2.N3(A0) ; port DDR_A_C.DDR_A0
DDR_A1: R2.1 U2.P7(A1) ; port DDR_A_C.DDR_A1
DDR_A2: R3.1 U2.P3(A2) ; port DDR_A_C.DDR_A2
DDR_A3: R4.1 U2.N2(A3) ; port DDR_A_C.DDR_A3
DDR_A4: R5.1 U2.P8(A4) ; port DDR_A_C.DDR_A4
DDR_A5: R6.1 U2.P2(A5) ; port DDR_A_C.DDR_A5
DDR_A6: R7.1 U2.R8(A6) ; port DDR_A_C.DDR_A6
DDR_A7: R8.1 U2.R2(A7) ; port DDR_A_C.DDR_A7
DDR_A8: R9.1 U2.T8(A8) ; port DDR_A_C.DDR_A8
DDR_A9: R10.1 U2.R3(A9) ; port DDR_A_C.DDR_A9
DDR_A10: R11.1 U2.L7(A10/AP) ; port DDR_A_C.DDR_A10
DDR_A11: R12.1 U2.R7(A11) ; port DDR_A_C.DDR_A11
DDR_A12: R13.1 U2.N7(A12/BC#) ; port DDR_A_C.DDR_A12
DDR_A13: R14.1 U2.T3(A13) ; port DDR_A_C.DDR_A13
DDR_A14: R15.1 U2.T7(A14) ; port DDR_A_C.DDR_A14
DDR_A15: R16.1 U2.M7(A15) ; port DDR_A_C.DDR_A15
DDR_BA0: R17.1 U2.M2(BA0) ; port DDR_A_C.DDR_BA0
DDR_BA1: R18.1 U2.N8(BA1) ; port DDR_A_C.DDR_BA1
DDR_BA2: R19.1 U2.M3(BA2) ; port DDR_A_C.DDR_BA2
DDR_CASN: R21.1 U2.K3(CAS#) ; port DDR_A_C.DDR_CASN
DDR_CKE: R23.1 R30.2 U2.K9(CKE) ; port DDR_A_C.DDR_CKE
DDR_CLK_N: R28.1 U2.K7(CK#) ; port DDR_A_C.DDR_CLK_N
DDR_CLK_P: R28.2 U2.J7(CK) ; port DDR_A_C.DDR_CLK_P
DDR_CSN: R22.1 U2.L2(CS#) ; port DDR_A_C.DDR_CSN
DDR_DQ0: U2.B8(DQU6) ; port DDR_BYTE0&1.DDR_DQ0
DDR_DQ1: U2.A7(DQU4) ; port DDR_BYTE0&1.DDR_DQ1
DDR_DQ2: U2.C2(DQU3) ; port DDR_BYTE0&1.DDR_DQ2
DDR_DQ3: U2.C8(DQU2) ; port DDR_BYTE0&1.DDR_DQ3
DDR_DQ4: U2.A3(DQU7) ; port DDR_BYTE0&1.DDR_DQ4
DDR_DQ5: U2.C3(DQU1) ; port DDR_BYTE0&1.DDR_DQ5
DDR_DQ6: U2.A2(DQU5) ; port DDR_BYTE0&1.DDR_DQ6
DDR_DQ7: U2.D7(DQU0) ; port DDR_BYTE0&1.DDR_DQ7
DDR_DQ8: U2.G2(DQL6) ; port DDR_BYTE0&1.DDR_DQ8
DDR_DQ9: U2.E3(DQL0) ; port DDR_BYTE0&1.DDR_DQ9
DDR_DQ10: U2.H3(DQL4) ; port DDR_BYTE0&1.DDR_DQ10
DDR_DQ11: U2.H8(DQL5) ; port DDR_BYTE0&1.DDR_DQ11
DDR_DQ12: U2.F8(DQL3) ; port DDR_BYTE0&1.DDR_DQ12
DDR_DQ13: U2.F2(DQL2) ; port DDR_BYTE0&1.DDR_DQ13
DDR_DQ14: U2.H7(DQL7) ; port DDR_BYTE0&1.DDR_DQ14
DDR_DQ15: U2.F7(DQL1) ; port DDR_BYTE0&1.DDR_DQ15
DDR_DQM0: U2.D3(DMU) ; port DDR_BYTE0&1.DDR_DQM0
DDR_DQM1: U2.E7(DML) ; port DDR_BYTE0&1.DDR_DQM1
DDR_DQS0_N: U2.B7(DQSU#) ; port DDR_BYTE0&1.DDR_DQS0_N
DDR_DQS0_P: U2.C7(DQSU) ; port DDR_BYTE0&1.DDR_DQS0_P
DDR_DQS1_N: U2.G3(DQSL#) ; port DDR_BYTE0&1.DDR_DQS1_N
DDR_DQS1_P: U2.F3(DQSL) ; port DDR_BYTE0&1.DDR_DQS1_P
DDR_ODT: R25.1 U2.K1(ODT) ; port DDR_A_C.DDR_ODT
DDR_RASN: R20.1 U2.J3(RAS#) ; port DDR_A_C.DDR_RASN
DDR_RESETN: R29.2 U2.T2(RESET#) ; port DDR_A_C.DDR_RESETN
DDR_WEN: R24.1 U2.L3(WE#) ; port DDR_A_C.DDR_WEN
NetR26_2: R26.2 U2.L8(ZQ)

Not connected (* = marked no-connect by the designer): U2 J1(NC)* J9(NC)* L1(NC)* L9(NC)*

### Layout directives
differential pair: DDR_DQS0_N, DDR_DQS0_P, DDR_DQS1_N, DDR_DQS1_P

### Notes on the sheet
- To connect to VDD_DDR power plane

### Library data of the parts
C1-C12 C17 C19-C28 C64 C73 C74 = MCD-00006: as C61 on sheet Power_MPU
C15 C16 = MCD-00099: as C18 on sheet Power_PMIC
C62 C63 = MCD-00100: as C29 on sheet Power_PMIC
R1-R25 = MCD-00118: Resistor,56R,0402,1%,1/16W; Manufacturer_Part_Number: RC0402FR-0756RL; Manufacturer: YAGEO; Provided_By: SUBCO; ECCN_US: EAR99; ECCN_EU: NEC
R26 = MCD-00120: as R27 on sheet STM32_MPU_IOs
R28 = MCD-00119: Resistor,100R,0402,1%,1/16W; Manufacturer_Part_Number: RC0402FR-07100RL; Manufacturer: YAGEO; Provided_By: SUBCO; ECCN_US: EAR99; ECCN_EU: NEC
R29 R30 = MCD-00053: as R40 on sheet eMMC
U2 = MCD-01811: Memory,DDR3L,4Gb,256Mbx16,933Mhz,1V35,TFBGA; Part_Type: IC; Manufacturer: NANYA; ECCN_US: tbd; Provided_By: SUBCO

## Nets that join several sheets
3V3: Power_PMIC (5 pins), eMMC (6 pins)
GND: Power_PMIC (28 pins), Power_MPU (143 pins), eMMC (17 pins), STM32_MPU_IOs (C72.1 R27.2 U1.T15), 1DDR3L_16bits (54 pins)
VDD: Power_PMIC (C38.2 L3.2 U4.31 U4.42), Power_MPU (28 pins), eMMC (8 pins), STM32_MPU_IOs (R37.1 R38.1)
VDD_CORE: Power_PMIC (C34.2 L1.2 U4.5), Power_MPU (51 pins)
VDD_DDR: Power_PMIC (5 pins), Power_MPU (19 pins), 1DDR3L_16bits (32 pins)
VDD_USB: Power_PMIC (C52.2 U4.39), Power_MPU (C71.2 U1.W12 U1.W15)
VDDA: Power_PMIC (C49.2 U4.20), Power_MPU (R42.1)
VREF_DDR: Power_PMIC (C45.2 U4.16), STM32_MPU_IOs (C72.2 U1.W16), 1DDR3L_16bits (C24.2 C25.2 U2.H1 U2.M8)
VTT_DDR: Power_PMIC (C46.2 U4.14), 1DDR3L_16bits (39 pins)
DDR_A0: STM32_MPU_IOs (U1.H18), 1DDR3L_16bits (R1.1 U2.N3)
DDR_A1: STM32_MPU_IOs (U1.M17), 1DDR3L_16bits (R2.1 U2.P7)
DDR_A2: STM32_MPU_IOs (U1.G18), 1DDR3L_16bits (R3.1 U2.P3)
DDR_A3: STM32_MPU_IOs (U1.F19), 1DDR3L_16bits (R4.1 U2.N2)
DDR_A4: STM32_MPU_IOs (U1.P17), 1DDR3L_16bits (R5.1 U2.P8)
DDR_A5: STM32_MPU_IOs (U1.H17), 1DDR3L_16bits (R6.1 U2.P2)
DDR_A6: STM32_MPU_IOs (U1.N16), 1DDR3L_16bits (R7.1 U2.R8)
DDR_A7: STM32_MPU_IOs (U1.E17), 1DDR3L_16bits (R8.1 U2.R2)
DDR_A8: STM32_MPU_IOs (U1.R17), 1DDR3L_16bits (R9.1 U2.T8)
DDR_A9: STM32_MPU_IOs (U1.G17), 1DDR3L_16bits (R10.1 U2.R3)
DDR_A10: STM32_MPU_IOs (U1.M19), 1DDR3L_16bits (R11.1 U2.L7)
DDR_A11: STM32_MPU_IOs (U1.M18), 1DDR3L_16bits (R12.1 U2.R7)
DDR_A12: STM32_MPU_IOs (U1.L17), 1DDR3L_16bits (R13.1 U2.N7)
DDR_A13: STM32_MPU_IOs (U1.F17), 1DDR3L_16bits (R14.1 U2.T3)
DDR_A14: STM32_MPU_IOs (U1.N18), 1DDR3L_16bits (R15.1 U2.T7)
DDR_A15: STM32_MPU_IOs (U1.L16), 1DDR3L_16bits (R16.1 U2.M7)
DDR_BA0: STM32_MPU_IOs (U1.G19), 1DDR3L_16bits (R17.1 U2.M2)
DDR_BA1: STM32_MPU_IOs (U1.N17), 1DDR3L_16bits (R18.1 U2.N8)
DDR_BA2: STM32_MPU_IOs (U1.J16), 1DDR3L_16bits (R19.1 U2.M3)
DDR_CASN: STM32_MPU_IOs (U1.K17), 1DDR3L_16bits (R21.1 U2.K3)
DDR_CKE: STM32_MPU_IOs (U1.P19), 1DDR3L_16bits (R23.1 R30.2 U2.K9)
DDR_CLK_N: STM32_MPU_IOs (U1.K19), 1DDR3L_16bits (R28.1 U2.K7)
DDR_CLK_P: STM32_MPU_IOs (U1.L19), 1DDR3L_16bits (R28.2 U2.J7)
DDR_CSN: STM32_MPU_IOs (U1.J18), 1DDR3L_16bits (R22.1 U2.L2)
DDR_DQ0: STM32_MPU_IOs (U1.A17), 1DDR3L_16bits (U2.B8)
DDR_DQ1: STM32_MPU_IOs (U1.A18), 1DDR3L_16bits (U2.A7)
DDR_DQ2: STM32_MPU_IOs (U1.D18), 1DDR3L_16bits (U2.C2)
DDR_DQ3: STM32_MPU_IOs (U1.B17), 1DDR3L_16bits (U2.C8)
DDR_DQ4: STM32_MPU_IOs (U1.E18), 1DDR3L_16bits (U2.A3)
DDR_DQ5: STM32_MPU_IOs (U1.D17), 1DDR3L_16bits (U2.C3)
DDR_DQ6: STM32_MPU_IOs (U1.D19), 1DDR3L_16bits (U2.A2)
DDR_DQ7: STM32_MPU_IOs (U1.B18), 1DDR3L_16bits (U2.D7)
DDR_DQ8: STM32_MPU_IOs (U1.P18), 1DDR3L_16bits (U2.G2)
DDR_DQ9: STM32_MPU_IOs (U1.T17), 1DDR3L_16bits (U2.E3)
DDR_DQ10: STM32_MPU_IOs (U1.R18), 1DDR3L_16bits (U2.H3)
DDR_DQ11: STM32_MPU_IOs (U1.V19), 1DDR3L_16bits (U2.H8)
DDR_DQ12: STM32_MPU_IOs (U1.W18), 1DDR3L_16bits (U2.F8)
DDR_DQ13: STM32_MPU_IOs (U1.T18), 1DDR3L_16bits (U2.F2)
DDR_DQ14: STM32_MPU_IOs (U1.V18), 1DDR3L_16bits (U2.H7)
DDR_DQ15: STM32_MPU_IOs (U1.W17), 1DDR3L_16bits (U2.F7)
DDR_DQM0: STM32_MPU_IOs (U1.C18), 1DDR3L_16bits (U2.D3)
DDR_DQM1: STM32_MPU_IOs (U1.U18), 1DDR3L_16bits (U2.E7)
DDR_DQS0_N: STM32_MPU_IOs (U1.B19), 1DDR3L_16bits (U2.B7)
DDR_DQS0_P: STM32_MPU_IOs (U1.C19), 1DDR3L_16bits (U2.C7)
DDR_DQS1_N: STM32_MPU_IOs (U1.T19), 1DDR3L_16bits (U2.G3)
DDR_DQS1_P: STM32_MPU_IOs (U1.U19), 1DDR3L_16bits (U2.F3)
DDR_ODT: STM32_MPU_IOs (U1.H19), 1DDR3L_16bits (R25.1 U2.K1)
DDR_RASN: STM32_MPU_IOs (U1.L18), 1DDR3L_16bits (R20.1 U2.J3)
DDR_RESETN: STM32_MPU_IOs (U1.G16), 1DDR3L_16bits (R29.2 U2.T2)
DDR_WEN: STM32_MPU_IOs (U1.J17), 1DDR3L_16bits (R24.1 U2.L3)
I2C4_SCL: Power_PMIC (U4.4), STM32_MPU_IOs (R37.2 U1.U11)
I2C4_SDA: Power_PMIC (U4.3), STM32_MPU_IOs (R38.2 U1.U12)
NRST: Power_PMIC (U4.1), STM32_MPU_IOs (U1.J1)
PA0_WKUP: Power_PMIC (U4.43), STM32_MPU_IOs (U1.R3)
PWR_ON: Power_PMIC (U4.44), STM32_MPU_IOs (U1.L1)

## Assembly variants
Example: not fitted R34 R42 R42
